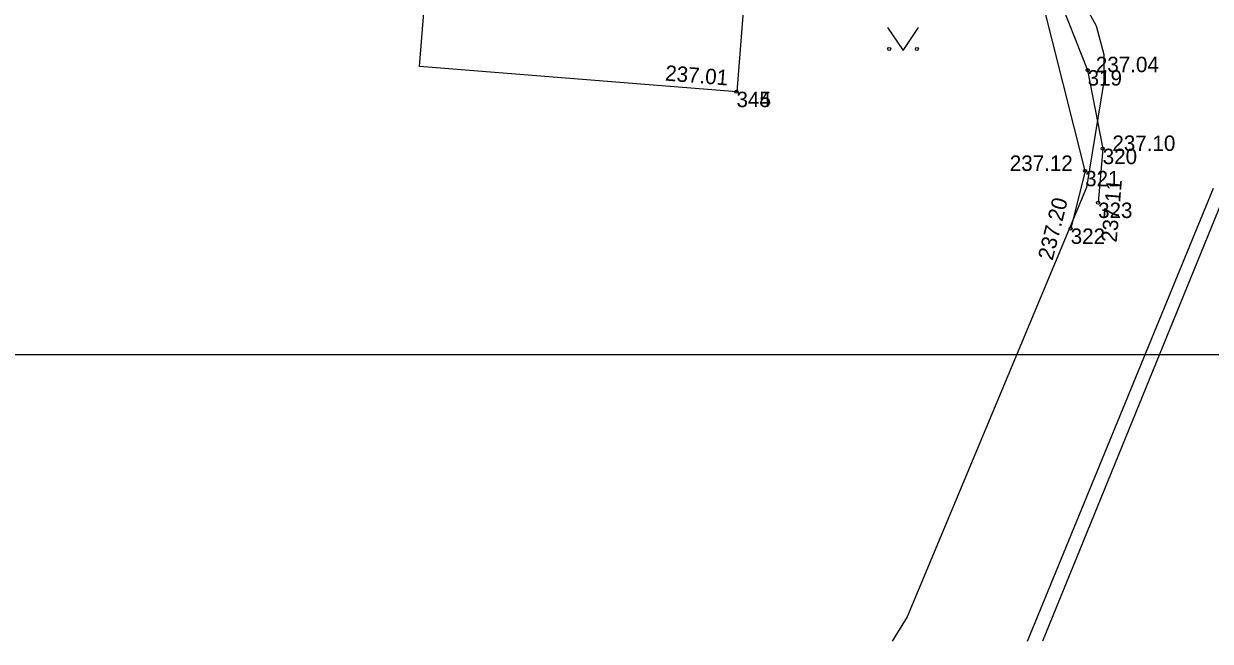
# Model space of a CAD drawing. Extents: x -596309 to -596099, y -1158697 to -1158513.
# Drawn here: x -596247.6 to -596209.08, y -1158697 to -1158676.95 of the extents above; entities that cross this region are included whole.
import ezdxf

# ---------------------------------------------------------------- set-up
doc = ezdxf.new("R2010")
doc.units = 0
for name, color, linetype in [('Vrstva 1', 7, 'Continuous'), ('Vrstva 10', 7, 'Continuous'), ('Vrstva 2', 7, 'Continuous'), ('Vrstva 3', 7, 'Continuous'), ('Vrstva 36', 7, 'Continuous'), ('Vrstva 5', 7, 'Continuous'), ('Vrstva 59', 7, 'Continuous'), ('Vrstva 63', 7, 'Continuous'), ('Vrstva 7', 7, 'Continuous'), ('Vrstva 8', 7, 'Continuous')]:
    doc.layers.add(name, color=color, linetype=linetype)

msp = doc.modelspace()

# ---------------------------------------------------------------- linework, layer by layer
at = {"layer": 'Vrstva 1'}
for p, q in [((-596213.2, -1158676.25), (-596212.78, -1158677.02)), ((-596212.78, -1158677.02), (-596212.53, -1158677.95)), ((-596212.53, -1158677.95), (-596212.53, -1158678.83)), ((-596212.53, -1158678.83), (-596212.81, -1158680.55)), ((-596212.81, -1158680.55), (-596213.1, -1158682.27)), ((-596213.1, -1158682.27), (-596218.92, -1158696.21)), ((-596215.007, -1158697), (-596208.97, -1158682.29)), ((-596208.61, -1158682.49), (-596214.526, -1158697)), ((-596218.92, -1158696.21), (-596219.41, -1158697))]:
    msp.add_line(p, q, dxfattribs=at)
at = {"layer": 'Vrstva 10'}
msp.add_lwpolyline([(-596234.91, -1158657.42), (-596235.54, -1158663.54), (-596235.64, -1158664.59), (-596236.28, -1158669.77), (-596224.72, -1158670.95), (-596219.27, -1158671.44), (-596219.31, -1158671.81), (-596217.76, -1158672.7), (-596216.62, -1158673.4), (-596215.57, -1158674.26), (-596214.79, -1158675.05), (-596213.89, -1158676.38), (-596213.06, -1158678.46), (-596212.57, -1158681.01), (-596212.72, -1158682.76)], dxfattribs=at)
at = {"layer": 'Vrstva 2'}
for centre in [(-596213.06, -1158678.46), (-596224.46, -1158679.16), (-596212.57, -1158681.01), (-596213.14, -1158681.73), (-596212.72, -1158682.76), (-596213.61, -1158683.6)]:
    msp.add_circle(centre, 0.05, dxfattribs=at)
at = {"layer": 'Vrstva 3'}
for p, q in [((-596213.06, -1158678.46), (-596213.059, -1158678.46)), ((-596224.46, -1158679.16), (-596224.459, -1158679.16)), ((-596224.46, -1158679.16), (-596224.459, -1158679.16)), ((-596212.57, -1158681.01), (-596212.569, -1158681.01)), ((-596213.14, -1158681.73), (-596213.139, -1158681.73)), ((-596212.72, -1158682.76), (-596212.719, -1158682.76)), ((-596213.61, -1158683.6), (-596213.609, -1158683.6))]:
    msp.add_line(p, q, dxfattribs=at)
at = {"layer": 'Vrstva 36'}
msp.add_lwpolyline([(-596219.553, -1158677.072), (-596219.053, -1158677.822), (-596218.553, -1158677.072)], dxfattribs=at)
for centre in [(-596219.503, -1158677.772), (-596218.603, -1158677.772)]:
    msp.add_circle(centre, 0.05, dxfattribs=at)
at = {"layer": 'Vrstva 5'}
msp.add_lwpolyline([(-596234.27, -1158672.28), (-596223.97, -1158673.1), (-596224.452, -1158679.161), (-596234.752, -1158678.341)], close=True, dxfattribs=at)
at = {"layer": 'Vrstva 63'}
msp.add_lwpolyline([(-596309.058, -1158687.689), (-596099.058, -1158687.689), (-596099.058, -1158539.189), (-596309.058, -1158539.189)], close=True, dxfattribs=at)
at = {"layer": 'Vrstva 7'}
msp.add_line((-596213.14, -1158681.73), (-596213.61, -1158683.6), dxfattribs=at)
at = {"layer": 'Vrstva 8'}
msp.add_line((-596213.14, -1158681.73), (-596214.81, -1158675.09), dxfattribs=at)

# ---------------------------------------------------------------- texts
at = {"layer": 'Vrstva 2'}
for s, p in [('237.04', (-596212.792, -1158678.526)), ('237.10', (-596212.256, -1158681.082)), ('237.12', (-596215.587, -1158681.73))]:
    msp.add_text(s, height=0.5, dxfattribs=at).set_placement(p)
for s, rotation, p in [('237.01', 355.4482, (-596226.791, -1158678.797)), ('237.11', 85.1009, (-596212.118, -1158684.064)), ('237.20', 75.8917, (-596214.198, -1158684.659))]:
    msp.add_text(s, height=0.5, rotation=rotation, dxfattribs=at).set_placement(p)
at = {"layer": 'Vrstva 59'}
for s, p in [('319', (-596213.06, -1158678.96)), ('344', (-596224.46, -1158679.66)), ('345', (-596224.46, -1158679.66)), ('320', (-596212.57, -1158681.51)), ('321', (-596213.14, -1158682.23)), ('323', (-596212.72, -1158683.26)), ('322', (-596213.61, -1158684.1))]:
    msp.add_text(s, height=0.5, dxfattribs=at).set_placement(p)

doc.saveas('drawing.dxf')
